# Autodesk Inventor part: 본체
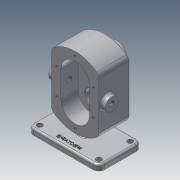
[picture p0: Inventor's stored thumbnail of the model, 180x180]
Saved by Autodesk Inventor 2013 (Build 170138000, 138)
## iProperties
Created: 2019-03
Part Number: 본체
Material: 알루미늄 6061
Document SubType Name: Modeling
Designer: Administrator
Density: 2.71 g/cm^3
Mass: 1191.51 g
Surface Area: 719.254 cm^2
Volume: 439.671 cm^3
Author: Administrator
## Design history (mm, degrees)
sketch "스케치1"
  geometry: L1 (-40, 44.721)-(-40, -44.721); L2 (40, 44.721)-(40, -44.721); A1 r 60 centre (0, 0) between (-40, -44.721) and (40, -44.721); A2 r 60 centre (0, 0) between (40, 44.721) and (-40, 44.721); 1 further point
  constraints: 4 end point, 4 point on circle, 2 centre point, 1 coincident, 1 parallel, 1 vertical
  dimensions: "d1" = 40 distance from line of A1.centre L1; "d2" = 40 distance from line of L2 point (0, 0); "d3" = 60 radius of A2; "d4" = 60 radius of A1
extrude "돌출1" new body sketch "스케치1" stored distance "d5" = 53; taper "d6" = 0 deg
sketch "스케치2"
  geometry: L1 (40, -44.721)-(40, 44.721) reference; L2 (0, 0)-(0, 78); L3 (60, 68)-(-60, 68); L4 (-60, 68)-(-60, 78); L5 (-60, 78)-(60, 78); L6 (60, 78)-(60, 68); A1 r 60 centre (0, 0) between (40, 44.721) and (-40, 44.721) reference
  constraints: 10 end point, 3 parallel, 1 horizontal, 1 midpoint, 1 perpendicular
  dimensions: "d7" = 78 distance of L2.end L2.start; "d8" = 120 distance of L4.end L5.end; "d9" = 10 distance of L3.end L4.end
extrude "돌출2" join sketch "스케치2" distance "d10" = 73; taper "d11" = 0 deg
sketch "스케치3"
  geometry: L1 (120, 0)-(0, 0) reference; L2 (54, 0)-(66, 0); L3 (66, 0)-(66, -43); L4 (66, -43)-(54, -43); L5 (54, -43)-(54, 0); 2 further points
  constraints: 8 end point, 2 midpoint, 2 parallel, 1 horizontal, 1 perpendicular
  dimensions: "d12" = 12 distance of L3.end L4.end; "d13" = 43 distance of L2.end L3.end
extrude "돌출3" join sketch "스케치3" stored distance "d14" = 73; taper "d15" = 0 deg
sketch "스케치4"
  geometry: L1 (-40, 44.721)-(-40, -44.721) reference; L2 (0, 0)-(0, -22); L3 (0, 0)-(0, 22); L4 (24, -22)-(24, 22); L5 (-24, -22)-(-24, 22); A1 r 60 centre (0, 0) between (-40, -44.721) and (40, -44.721) reference; A2 r 24 centre (0, -22) between (24, -22) and (-24, -22); A3 r 24 centre (0, 22) between (24, 22) and (-24, 22)
  constraints: 8 end point, 4 point on circle, 3 tangent, 2 centre point, 2 coincident, 2 parallel, 1 collinear
  dimensions: "d16" = 22 distance of L2.start L2.end; "d17" = 22 distance of L2.start L3.end; "d18" = 48 diameter of A2; "d19" = 48 diameter of A3
extrude "돌출4" cut sketch "스케치4" distance "d20" = 29; taper "d21" = 0 deg
sketch "스케치5"
  geometry: C1 r 12.5 at (0, 22); A1 r 24 centre (0, 22) between (24, 22) and (-24, 22) reference; 1 further point
  constraints: 1 centre point, 1 coincident
  dimensions: "d22" = 25 diameter of C1
extrude "돌출5" cut sketch "스케치5" distance "d23" = 15; taper "d24" = 0 deg
sketch "스케치6"
  geometry: C1 r 12.5 at (0, -22); A1 r 24 centre (0, -22) between (-24, -22) and (24, -22) reference; 1 further point
  constraints: 1 centre point, 1 coincident
  dimensions: "d25" = 25 diameter of C1
extrude "돌출6" cut sketch "스케치6" distance "d26" = 15; taper "d27" = 0 deg
sketch "스케치7"
  geometry: L1 (6, 68)-(6, 59.699) reference; L2 (0, 0)-(0, -22); C1 r 19 at (0, -22); A1 r 60 centre (0, 0) between (40, 44.721) and (6, 59.699) reference
  constraints: 2 end point, 1 centre point, 1 coincident, 1 parallel
  dimensions: "d28" = 22 distance of L2.start L2.end; "d29" = 38 diameter of C1
extrude "돌출7" join sketch "스케치7" distance "d30" = 17; taper "d31" = 0 deg
sketch "스케치8"
  geometry: C1 r 19 at (0, 0) reference; C2 r 14 at (0, 0); 1 further point
  constraints: 1 centre point, 1 coincident
  dimensions: "d32" = 28 diameter of C2
extrude "돌출8" cut sketch "스케치8" distance "d33" = 7.3; taper "d34" = 0 deg
sketch "스케치9"
  geometry: C1 r 14 at (0, 0) reference; C2 r 8.5 at (0, 0); 1 further point
  constraints: 1 centre point, 1 coincident
  dimensions: "d35" = 17 diameter of C2
extrude "돌출9" cut sketch "스케치9" stored distance "d36" = 7.3; taper "d37" = 0 deg
fillet "모깎기1" dims "d38" = 10
sketch "스케치10"
  geometry: A1 r 24 centre (0, 22) between (24, 22) and (-24, 22) reference; A2 r 24 centre (0, -22) between (-24, -22) and (24, -22) reference; A3 r 31 centre (0, -22) between (0, -53) and (31, -22); A4 r 31 centre (0, 22) between (-31, 22) and (31, 22); 2 further points
  constraints: 6 point on circle, 2 centre point, 2 coincident
  dimensions: "d39" = 62 diameter of A3; "d40" = 62 diameter of A4
hole "구멍1" sketch "스케치10" at (0, -53), (31, -22), (-31, -22), (-31, 22), (31, 22), (0, 53) diameter "d41" = 4.134; stored, may be unused: countersink angle "d45" = 90 deg, drill point angle "d47" = 118 deg; dims "d42" = 10, "d43" = 4, "d44" = 2, "d46" = 12
sketch "스케치11"
  geometry: L1 (53, 89.443)-(53, 0) reference; L2 (10, 122.721)-(63, 122.721) reference; C1 r 11 at (39, 44.721); 1 further point
  constraints: 1 centre point
  dimensions: "d48" = 22 diameter of C1; "d49" = 78 distance from line of C1.centre L2; "d50" = 14 distance from line of C1.centre L1
extrude "돌출10" join sketch "스케치11" distance "d51" = 8; taper "d52" = 0 deg
sketch "스케치12"
  geometry: C1 r 11 at (0, 0) reference; 2 further points
  constraints: 1 coincident
hole "구멍2" sketch "스케치12" at (0, 0) diameter "d53" = 8.376; stored, may be unused: countersink angle "d57" = 90 deg, drill point angle "d59" = 118 deg; dims "d54" = 10, "d55" = 4, "d56" = 2, "d58" = 12
sketch "스케치13"
  geometry: C1 r 4.5 at (-44, 33); C2 r 4.5 at (56, 33); C3 r 4.5 at (56, -20); C4 r 4.5 at (-44, -20); A1 r 10 centre (-44, 33) between (-44, 43) and (-54, 33) reference; A2 r 10 centre (-44, -20) between (-54, -20) and (-44, -30) reference; A3 r 10 centre (56, -20) between (56, -30) and (66, -20) reference; A4 r 10 centre (56, 33) between (66, 33) and (56, 43) reference; 1 further point
  constraints: 4 centre point, 4 coincident
  dimensions: "d60" = 9 diameter of C1; "d61" = 9 diameter of C2; "d62" = 9 diameter of C3; "d63" = 9 diameter of C4
extrude "돌출11" cut sketch "스케치13" stored distance "d64" = 8; taper "d65" = 0 deg
fillet "모깎기2" dims "d66" = 10
chamfer "모따기1" distance "d67" = 1; stored, may be unused: second distance "d68" = 2, angle "d69" = 45 deg
chamfer "모따기2" distance "d70" = 0.7; stored, may be unused: second distance "d71" = 2, angle "d72" = 30 deg
fillet "모깎기3" dims "d73" = 0.5
fillet "모깎기4" dims "d74" = 3
fillet "모깎기5" dims "d75" = 3
fillet "모깎기6" dims "d76" = 3
fillet "모깎기7" dims "d77" = 3
fillet "모깎기8" dims "d78" = 3
sketch "스케치14"
  geometry: L1 (-10, 60)-(-10, 7) reference; A1 r 7 centre (0, 7) between (-7, 7) and (0, 0) reference; 2 further points
  constraints: 1 horizontal alignment, 1 other
  dimensions: "d79" = 60 distance from line of point (50, 7) L1
feature "엠보싱1" sketch "스케치14" dims "d80" = 0.5, "d81" = 0
fillet "모깎기9" dims "d82" = 3
node "솔리드1"
mirror "대칭1"
